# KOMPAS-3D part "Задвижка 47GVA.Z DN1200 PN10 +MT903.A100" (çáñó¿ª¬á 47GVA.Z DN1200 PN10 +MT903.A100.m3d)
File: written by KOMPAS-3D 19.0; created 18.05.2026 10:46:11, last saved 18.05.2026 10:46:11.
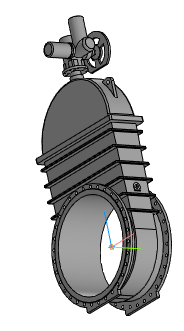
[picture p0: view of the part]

Document properties: Автор: Энергия; Полное имя файла: ..\Задвижка 47GVA.Z DN350_DN1200+MT903.A\Задвижка 47GVA.Z DN1200 PN10 +MT903.A100.a3d

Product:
- Part/product: Задвижка 47GVA.Z DN1200 PN10 +MT903.A100
    Масса: 6780.66
  - Body: Электропривод МТ903.А100 без блока управления
      Масса: 346.451
  - Body: Задвижка 47GVA.Z DN1200 PN10 без исполнит. мех.
      Масса: 6434.21

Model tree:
1. Операция без истории:1
2. Операция без истории:2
